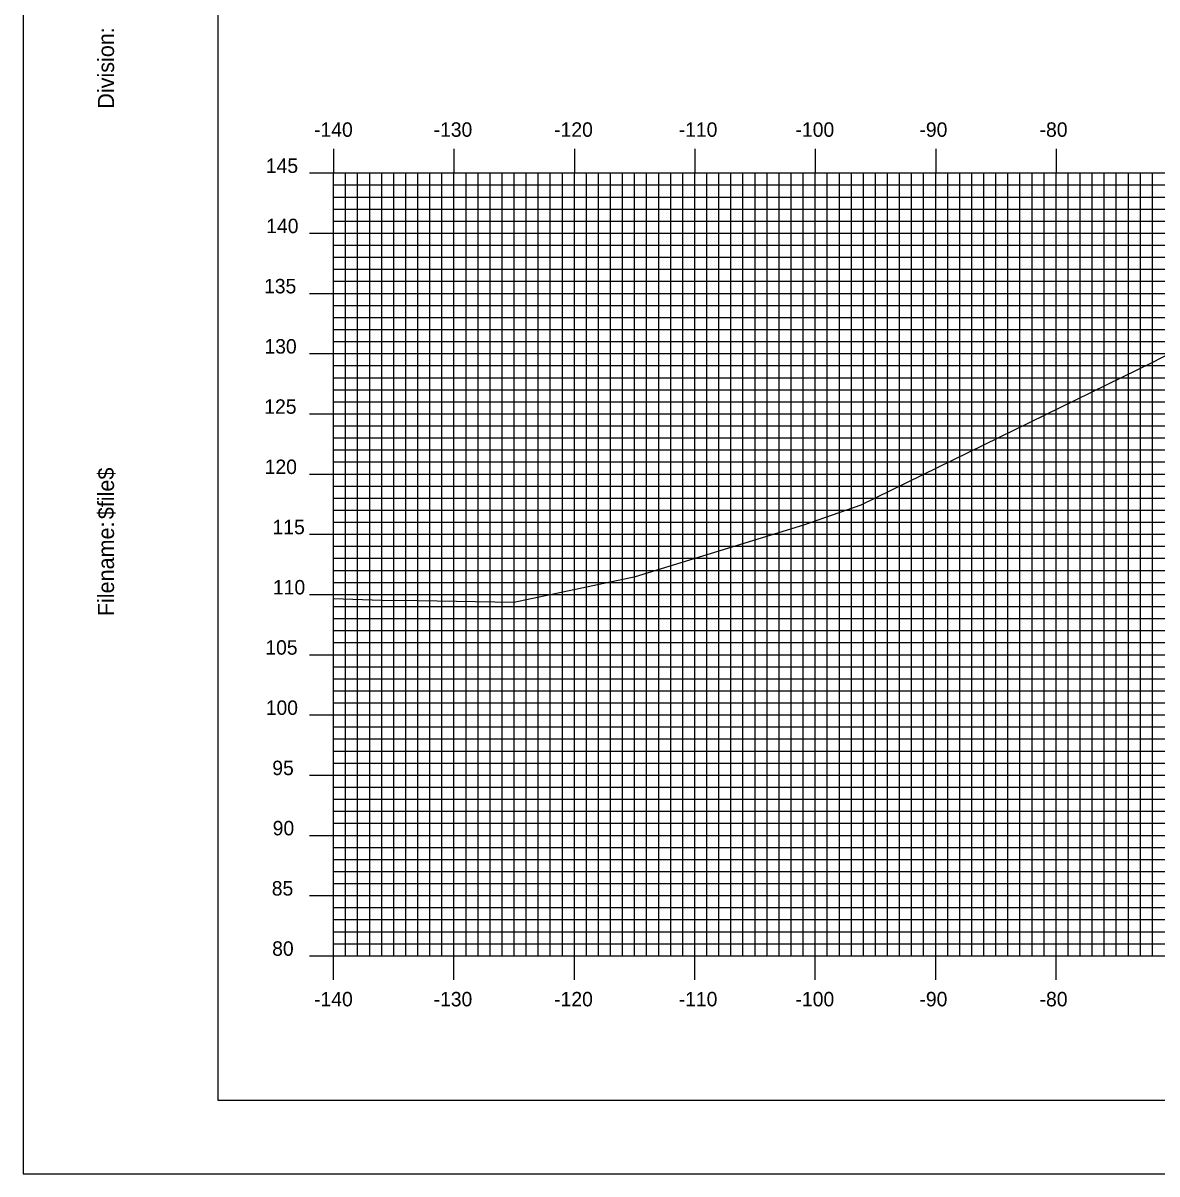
# Model space of a CAD drawing. Extents: x 859865 to 860208, y 364765 to 364985.
# Drawn here: x 859864.6 to 859958.8, y 364765.2 to 364860.7 of the extents above; entities that cross this region are included whole.
import ezdxf

# ---------------------------------------------------------------- set-up
doc = ezdxf.new("R2010")
doc.units = 0
for name, color, linetype in [('BORDER', 7, 'Continuous'), ('H_V ANNOTATION', 7, 'Continuous'), ('MAJOR', 7, 'Continuous'), ('MINOR', 7, 'Continuous'), ('PLOT BOUNDARY', 7, 'Continuous'), ('S_Roadway_Centerline', 7, 'Continuous')]:
    doc.layers.add(name, color=color, linetype=linetype)

msp = doc.modelspace()

# ---------------------------------------------------------------- linework, layer by layer
at = {"layer": 'BORDER'}
msp.add_lwpolyline([(859880.786, 364771.302), (860200.786, 364771.302), (860200.786, 364981.302), (859880.786, 364981.302)], close=True, dxfattribs=at)
at = {"layer": 'MAJOR'}
for p, q in [((859890.386, 364850.306), (859890.386, 364848.302)), ((859900.386, 364850.306), (859900.386, 364848.302)), ((859910.386, 364850.306), (859910.386, 364848.302)), ((859920.386, 364850.306), (859920.386, 364848.302)), ((859930.386, 364850.306), (859930.386, 364848.302)), ((859940.386, 364850.306), (859940.386, 364848.302)), ((859950.386, 364850.306), (859950.386, 364848.302)), ((859888.382, 364848.302), (859890.386, 364848.302)), ((859890.386, 364848.302), (860170.386, 364848.302)), ((859890.386, 364783.302), (859890.386, 364848.302)), ((859890.386, 364783.302), (859890.386, 364848.302)), ((859890.386, 364848.302), (860170.386, 364848.302)), ((859900.386, 364783.302), (859900.386, 364848.302)), ((859910.386, 364783.302), (859910.386, 364848.302)), ((859920.386, 364783.302), (859920.386, 364848.302)), ((859930.386, 364783.302), (859930.386, 364848.302)), ((859940.386, 364783.302), (859940.386, 364848.302)), ((859950.386, 364783.302), (859950.386, 364848.302)), ((859888.382, 364843.302), (859890.386, 364843.302)), ((859890.386, 364843.302), (860170.386, 364843.302)), ((859888.382, 364838.302), (859890.386, 364838.302)), ((859890.386, 364838.302), (860170.386, 364838.302)), ((859888.382, 364833.302), (859890.386, 364833.302)), ((859890.386, 364833.302), (860170.386, 364833.302)), ((859888.382, 364828.302), (859890.386, 364828.302)), ((859890.386, 364828.302), (860170.386, 364828.302)), ((859888.382, 364823.302), (859890.386, 364823.302)), ((859890.386, 364823.302), (860170.386, 364823.302)), ((859888.382, 364818.302), (859890.386, 364818.302)), ((859890.386, 364818.302), (860170.386, 364818.302)), ((859888.382, 364813.302), (859890.386, 364813.302)), ((859890.386, 364813.302), (860170.386, 364813.302)), ((859888.382, 364808.302), (859890.386, 364808.302)), ((859890.386, 364808.302), (860170.386, 364808.302)), ((859888.382, 364803.302), (859890.386, 364803.302)), ((859890.386, 364803.302), (860170.386, 364803.302)), ((859888.382, 364798.302), (859890.386, 364798.302)), ((859890.386, 364798.302), (860170.386, 364798.302)), ((859888.382, 364793.302), (859890.386, 364793.302)), ((859890.386, 364793.302), (860170.386, 364793.302)), ((859888.382, 364788.302), (859890.386, 364788.302)), ((859890.386, 364788.302), (860170.386, 364788.302)), ((859888.382, 364783.302), (859890.386, 364783.302)), ((859890.386, 364783.302), (860170.386, 364783.302)), ((859890.386, 364783.302), (860170.386, 364783.302)), ((859890.386, 364781.298), (859890.386, 364783.302)), ((859900.386, 364781.298), (859900.386, 364783.302)), ((859910.386, 364781.298), (859910.386, 364783.302)), ((859920.386, 364781.298), (859920.386, 364783.302)), ((859930.386, 364781.298), (859930.386, 364783.302)), ((859940.386, 364781.298), (859940.386, 364783.302)), ((859950.386, 364781.298), (859950.386, 364783.302))]:
    msp.add_line(p, q, dxfattribs=at)
at = {"layer": 'MINOR'}
for p, q in [((859891.386, 364783.302), (859891.386, 364848.302)), ((859892.386, 364783.302), (859892.386, 364848.302)), ((859893.386, 364783.302), (859893.386, 364848.302)), ((859894.386, 364783.302), (859894.386, 364848.302)), ((859895.386, 364783.302), (859895.386, 364848.302)), ((859896.386, 364783.302), (859896.386, 364848.302)), ((859897.386, 364783.302), (859897.386, 364848.302)), ((859898.386, 364783.302), (859898.386, 364848.302)), ((859899.386, 364783.302), (859899.386, 364848.302)), ((859901.386, 364783.302), (859901.386, 364848.302)), ((859902.386, 364783.302), (859902.386, 364848.302)), ((859903.386, 364783.302), (859903.386, 364848.302)), ((859904.386, 364783.302), (859904.386, 364848.302)), ((859905.386, 364783.302), (859905.386, 364848.302)), ((859906.386, 364783.302), (859906.386, 364848.302)), ((859907.386, 364783.302), (859907.386, 364848.302)), ((859908.386, 364783.302), (859908.386, 364848.302)), ((859909.386, 364783.302), (859909.386, 364848.302)), ((859911.386, 364783.302), (859911.386, 364848.302)), ((859912.386, 364783.302), (859912.386, 364848.302)), ((859913.386, 364783.302), (859913.386, 364848.302)), ((859914.386, 364783.302), (859914.386, 364848.302)), ((859915.386, 364783.302), (859915.386, 364848.302)), ((859916.386, 364783.302), (859916.386, 364848.302)), ((859917.386, 364783.302), (859917.386, 364848.302)), ((859918.386, 364783.302), (859918.386, 364848.302)), ((859919.386, 364783.302), (859919.386, 364848.302)), ((859921.386, 364783.302), (859921.386, 364848.302)), ((859922.386, 364783.302), (859922.386, 364848.302)), ((859923.386, 364783.302), (859923.386, 364848.302)), ((859924.386, 364783.302), (859924.386, 364848.302)), ((859925.386, 364783.302), (859925.386, 364848.302)), ((859926.386, 364783.302), (859926.386, 364848.302)), ((859927.386, 364783.302), (859927.386, 364848.302)), ((859928.386, 364783.302), (859928.386, 364848.302)), ((859929.386, 364783.302), (859929.386, 364848.302)), ((859931.386, 364783.302), (859931.386, 364848.302)), ((859932.386, 364783.302), (859932.386, 364848.302)), ((859933.386, 364783.302), (859933.386, 364848.302)), ((859934.386, 364783.302), (859934.386, 364848.302)), ((859935.386, 364783.302), (859935.386, 364848.302)), ((859936.386, 364783.302), (859936.386, 364848.302)), ((859937.386, 364783.302), (859937.386, 364848.302)), ((859938.386, 364783.302), (859938.386, 364848.302)), ((859939.386, 364783.302), (859939.386, 364848.302)), ((859941.386, 364783.302), (859941.386, 364848.302)), ((859942.386, 364783.302), (859942.386, 364848.302)), ((859943.386, 364783.302), (859943.386, 364848.302)), ((859944.386, 364783.302), (859944.386, 364848.302)), ((859945.386, 364783.302), (859945.386, 364848.302)), ((859946.386, 364783.302), (859946.386, 364848.302)), ((859947.386, 364783.302), (859947.386, 364848.302)), ((859948.386, 364783.302), (859948.386, 364848.302)), ((859949.386, 364783.302), (859949.386, 364848.302)), ((859951.386, 364783.302), (859951.386, 364848.302)), ((859952.386, 364783.302), (859952.386, 364848.302)), ((859953.386, 364783.302), (859953.386, 364848.302)), ((859954.386, 364783.302), (859954.386, 364848.302)), ((859955.386, 364783.302), (859955.386, 364848.302)), ((859956.386, 364783.302), (859956.386, 364848.302)), ((859957.386, 364783.302), (859957.386, 364848.302)), ((859958.386, 364783.302), (859958.386, 364848.302)), ((859890.386, 364847.302), (860170.386, 364847.302)), ((859890.386, 364847.302), (859892.39, 364847.302)), ((859890.386, 364846.302), (860170.386, 364846.302)), ((859890.386, 364846.302), (859892.39, 364846.302)), ((859890.386, 364845.302), (860170.386, 364845.302)), ((859890.386, 364845.302), (859892.39, 364845.302)), ((859890.386, 364844.302), (860170.386, 364844.302)), ((859890.386, 364844.302), (859892.39, 364844.302)), ((859890.386, 364842.302), (860170.386, 364842.302)), ((859890.386, 364842.302), (859892.39, 364842.302)), ((859890.386, 364841.302), (860170.386, 364841.302)), ((859890.386, 364841.302), (859892.39, 364841.302)), ((859890.386, 364840.302), (860170.386, 364840.302)), ((859890.386, 364840.302), (859892.39, 364840.302)), ((859890.386, 364839.302), (860170.386, 364839.302)), ((859890.386, 364839.302), (859892.39, 364839.302)), ((859890.386, 364837.302), (860170.386, 364837.302)), ((859890.386, 364837.302), (859892.39, 364837.302)), ((859890.386, 364836.302), (860170.386, 364836.302)), ((859890.386, 364836.302), (859892.39, 364836.302)), ((859890.386, 364835.302), (860170.386, 364835.302)), ((859890.386, 364835.302), (859892.39, 364835.302)), ((859890.386, 364834.302), (860170.386, 364834.302)), ((859890.386, 364834.302), (859892.39, 364834.302)), ((859890.386, 364832.302), (860170.386, 364832.302)), ((859890.386, 364832.302), (859892.39, 364832.302)), ((859890.386, 364831.302), (860170.386, 364831.302)), ((859890.386, 364831.302), (859892.39, 364831.302)), ((859890.386, 364830.302), (860170.386, 364830.302)), ((859890.386, 364830.302), (859892.39, 364830.302)), ((859890.386, 364829.302), (860170.386, 364829.302)), ((859890.386, 364829.302), (859892.39, 364829.302)), ((859890.386, 364827.302), (860170.386, 364827.302)), ((859890.386, 364827.302), (859892.39, 364827.302)), ((859890.386, 364826.302), (860170.386, 364826.302)), ((859890.386, 364826.302), (859892.39, 364826.302)), ((859890.386, 364825.302), (860170.386, 364825.302)), ((859890.386, 364825.302), (859892.39, 364825.302)), ((859890.386, 364824.302), (860170.386, 364824.302)), ((859890.386, 364824.302), (859892.39, 364824.302)), ((859890.386, 364822.302), (860170.386, 364822.302)), ((859890.386, 364822.302), (859892.39, 364822.302)), ((859890.386, 364821.302), (860170.386, 364821.302)), ((859890.386, 364821.302), (859892.39, 364821.302)), ((859890.386, 364820.302), (860170.386, 364820.302)), ((859890.386, 364820.302), (859892.39, 364820.302)), ((859890.386, 364819.302), (860170.386, 364819.302)), ((859890.386, 364819.302), (859892.39, 364819.302)), ((859890.386, 364817.302), (860170.386, 364817.302)), ((859890.386, 364817.302), (859892.39, 364817.302)), ((859890.386, 364816.302), (860170.386, 364816.302)), ((859890.386, 364816.302), (859892.39, 364816.302)), ((859890.386, 364815.302), (860170.386, 364815.302)), ((859890.386, 364815.302), (859892.39, 364815.302)), ((859890.386, 364814.302), (860170.386, 364814.302)), ((859890.386, 364814.302), (859892.39, 364814.302)), ((859890.386, 364812.302), (860170.386, 364812.302)), ((859890.386, 364812.302), (859892.39, 364812.302)), ((859890.386, 364811.302), (860170.386, 364811.302)), ((859890.386, 364811.302), (859892.39, 364811.302)), ((859890.386, 364810.302), (860170.386, 364810.302)), ((859890.386, 364810.302), (859892.39, 364810.302)), ((859890.386, 364809.302), (860170.386, 364809.302)), ((859890.386, 364809.302), (859892.39, 364809.302)), ((859890.386, 364807.302), (860170.386, 364807.302)), ((859890.386, 364807.302), (859892.39, 364807.302)), ((859890.386, 364806.302), (860170.386, 364806.302)), ((859890.386, 364806.302), (859892.39, 364806.302)), ((859890.386, 364805.302), (860170.386, 364805.302)), ((859890.386, 364805.302), (859892.39, 364805.302)), ((859890.386, 364804.302), (860170.386, 364804.302)), ((859890.386, 364804.302), (859892.39, 364804.302)), ((859890.386, 364802.302), (860170.386, 364802.302)), ((859890.386, 364802.302), (859892.39, 364802.302)), ((859890.386, 364801.302), (860170.386, 364801.302)), ((859890.386, 364801.302), (859892.39, 364801.302)), ((859890.386, 364800.302), (860170.386, 364800.302)), ((859890.386, 364800.302), (859892.39, 364800.302)), ((859890.386, 364799.302), (860170.386, 364799.302)), ((859890.386, 364799.302), (859892.39, 364799.302)), ((859890.386, 364797.302), (860170.386, 364797.302)), ((859890.386, 364797.302), (859892.39, 364797.302)), ((859890.386, 364796.302), (860170.386, 364796.302)), ((859890.386, 364796.302), (859892.39, 364796.302)), ((859890.386, 364795.302), (860170.386, 364795.302)), ((859890.386, 364795.302), (859892.39, 364795.302)), ((859890.386, 364794.302), (860170.386, 364794.302)), ((859890.386, 364794.302), (859892.39, 364794.302)), ((859890.386, 364792.302), (860170.386, 364792.302)), ((859890.386, 364792.302), (859892.39, 364792.302)), ((859890.386, 364791.302), (860170.386, 364791.302)), ((859890.386, 364791.302), (859892.39, 364791.302)), ((859890.386, 364790.302), (860170.386, 364790.302)), ((859890.386, 364790.302), (859892.39, 364790.302)), ((859890.386, 364789.302), (860170.386, 364789.302)), ((859890.386, 364789.302), (859892.39, 364789.302)), ((859890.386, 364787.302), (860170.386, 364787.302)), ((859890.386, 364787.302), (859892.39, 364787.302)), ((859890.386, 364786.302), (860170.386, 364786.302)), ((859890.386, 364786.302), (859892.39, 364786.302)), ((859890.386, 364785.302), (860170.386, 364785.302)), ((859890.386, 364785.302), (859892.39, 364785.302)), ((859890.386, 364784.302), (860170.386, 364784.302)), ((859890.386, 364784.302), (859892.39, 364784.302))]:
    msp.add_line(p, q, dxfattribs=at)
at = {"layer": 'PLOT BOUNDARY'}
msp.add_lwpolyline([(859864.6, 364765.184), (860204.6, 364765.184), (860204.6, 364985.184), (859864.6, 364985.184)], close=True, dxfattribs=at)
at = {"layer": 'S_Roadway_Centerline'}
msp.add_lwpolyline([(859890.386, 364812.971), (859894.391, 364812.833), (859897.423, 364812.789), (859905.344, 364812.655), (859915.458, 364814.796), (859929.437, 364819.075), (859934.194, 364820.746), (859958.408, 364832.58), (859968.226, 364837.682), (859979.732, 364838.329), (859988.281, 364838.781), (860006.532, 364839.396), (860017.485, 364839.72), (860027.043, 364839.866), (860038.428, 364840.091), (860049.995, 364834.792), (860076.156, 364822.232)], dxfattribs=at)

# ---------------------------------------------------------------- texts
at = {"layer": 'BORDER'}
for s, p in [('Division:', (859872.156, 364853.634)), ('$file$', (859872.156, 364819.553)), ('Filename:', (859872.156, 364811.499))]:
    msp.add_text(s, height=1.3392, rotation=90, dxfattribs=at).set_placement(p)
at = {"layer": 'H_V ANNOTATION'}
for s, p in [('-140', (859888.77, 364851.302)), ('-130', (859898.695, 364851.302)), ('-120', (859908.706, 364851.302)), ('-110', (859919.048, 364851.302)), ('-100', (859928.749, 364851.302)), ('-90', (859939.038, 364851.302)), ('-80', (859949.016, 364851.302)), ('145', (859884.764, 364848.302)), ('145', (859884.764, 364848.302)), ('140', (859884.796, 364843.302)), ('140', (859884.796, 364843.302)), ('135', (859884.614, 364838.302)), ('135', (859884.614, 364838.302)), ('130', (859884.646, 364833.302)), ('130', (859884.646, 364833.302)), ('125', (859884.635, 364828.302)), ('125', (859884.635, 364828.302)), ('120', (859884.667, 364823.302)), ('120', (859884.667, 364823.302)), ('115', (859885.321, 364818.302)), ('110', (859885.353, 364813.302)), ('105', (859884.721, 364808.302)), ('105', (859884.721, 364808.302)), ('100', (859884.753, 364803.302)), ('100', (859884.753, 364803.302)), ('95', (859885.299, 364798.302)), ('90', (859885.331, 364793.302)), ('85', (859885.256, 364788.302)), ('80', (859885.288, 364783.302)), ('-140', (859888.77, 364779.102)), ('-130', (859898.695, 364779.102)), ('-120', (859908.706, 364779.102)), ('-110', (859919.048, 364779.102)), ('-100', (859928.749, 364779.102)), ('-90', (859939.038, 364779.102)), ('-80', (859949.016, 364779.102))]:
    msp.add_text(s, height=1.2, dxfattribs=at).set_placement(p)
at = {"layer": 'MAJOR'}
msp.add_text('-', height=0.012, dxfattribs=at).set_placement((859890.377, 364783.302))

doc.saveas('drawing.dxf')
